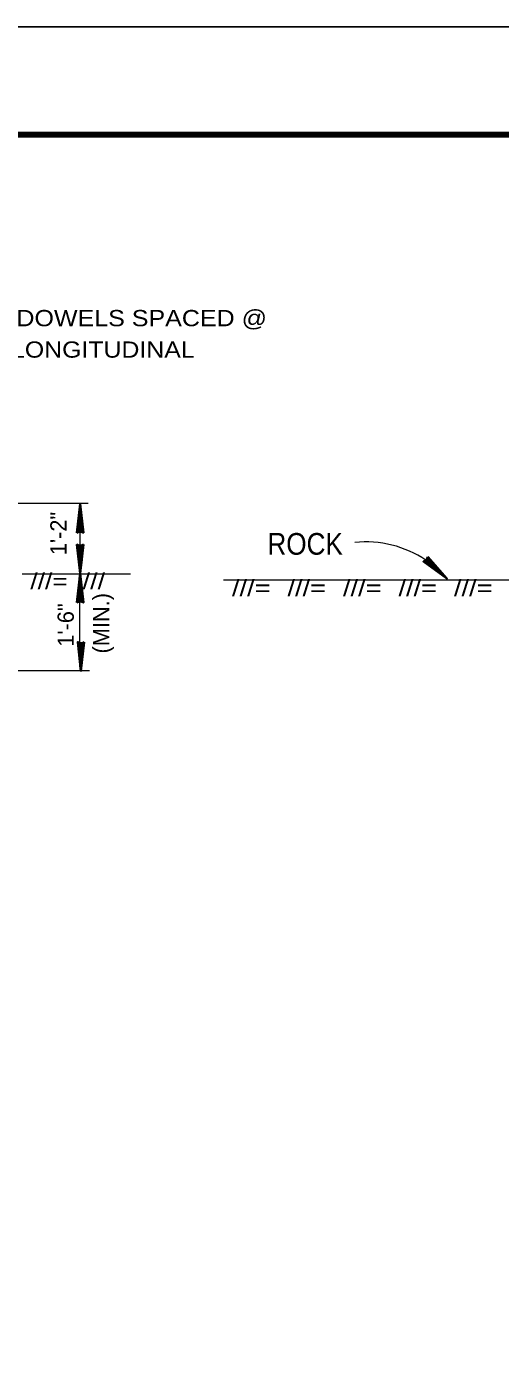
# Model space of a CAD drawing. Extents: x 1.6 to 19.9, y 2.8 to 9.5.
# Drawn here: x 18.367 to 18.709, y 8.58 to 9.545 of the extents above; entities that cross this region are included whole.
import ezdxf
from ezdxf.enums import TextEntityAlignment as Align

# ---------------------------------------------------------------- set-up
doc = ezdxf.new("R2010")
doc.units = 0
doc.header["$LTSCALE"] = 0.0047
doc.layers.add('1', color=7, linetype='Continuous', lineweight=35)
doc.layers.add('5', color=7, linetype='Continuous', lineweight=13)

msp = doc.modelspace()

# ---------------------------------------------------------------- linework, layer by layer
at = {"layer": '1', "lineweight": 25}
msp.add_line((19.894917, 9.545083), (16.26675, 9.545083), dxfattribs=at)
at = {"layer": '1', "lineweight": 13}
for p, q in [((18.209667, 9.20125), (18.411667, 9.20125)), ((18.405917, 9.1505), (18.405917, 9.198833)), ((18.402917, 9.15025), (18.411667, 9.15025)), ((18.40575, 9.083167), (18.40575, 9.149083)), ((18.22175, 9.0805), (18.412583, 9.0805))]:
    msp.add_line(p, q, dxfattribs=at)
at = {"layer": '1'}
for p, q in [((18.405917, 9.179833), (18.405917, 9.20075)), ((18.403917, 9.180333), (18.4055, 9.195917)), ((18.403917, 9.18025), (18.405583, 9.195917)), ((18.404, 9.18025), (18.405667, 9.195917)), ((18.404167, 9.18025), (18.405833, 9.19575)), ((18.404333, 9.18025), (18.406, 9.19575)), ((18.40725, 9.180167), (18.405583, 9.19475)), ((18.407417, 9.18025), (18.405917, 9.19475)), ((18.407667, 9.18025), (18.406167, 9.19475)), ((18.407917, 9.180333), (18.406333, 9.194833)), ((18.405917, 9.171333), (18.405917, 9.1505)), ((18.403917, 9.170917), (18.4055, 9.156333)), ((18.404167, 9.171), (18.405667, 9.156417)), ((18.404333, 9.171), (18.405917, 9.156417)), ((18.404583, 9.171), (18.406167, 9.1565)), ((18.407417, 9.171), (18.405833, 9.155417)), ((18.407667, 9.171), (18.406, 9.155417)), ((18.407917, 9.171), (18.406167, 9.155333)), ((18.40775, 9.171), (18.406167, 9.155333)), ((18.407917, 9.170917), (18.406333, 9.155333)), ((18.656667, 9.16175), (18.667083, 9.15)), ((18.656833, 9.161833), (18.66725, 9.150083)), ((18.656917, 9.161917), (18.667333, 9.15025)), ((18.657, 9.162), (18.667417, 9.15025)), ((18.657083, 9.162), (18.667417, 9.150333)), ((18.404917, 9.160167), (18.40575, 9.15325)), ((18.405083, 9.160167), (18.405833, 9.153417)), ((18.405167, 9.160167), (18.405917, 9.153417)), ((18.40525, 9.160167), (18.406083, 9.153417)), ((18.406667, 9.160167), (18.405833, 9.152833)), ((18.405917, 9.160333), (18.405917, 9.150583)), ((18.40675, 9.160167), (18.405917, 9.152833)), ((18.40675, 9.160167), (18.406, 9.152833)), ((18.406833, 9.160167), (18.406083, 9.152833)), ((18.406833, 9.160167), (18.406083, 9.152833)), ((18.654333, 9.159), (18.666167, 9.1505)), ((18.654417, 9.159167), (18.666333, 9.150667)), ((18.654583, 9.159417), (18.666417, 9.15075)), ((18.65475, 9.159667), (18.6665, 9.151)), ((18.655417, 9.16075), (18.670833, 9.14675)), ((18.403917, 9.13), (18.4055, 9.1455)), ((18.403917, 9.129833), (18.405583, 9.1455)), ((18.404, 9.129833), (18.405667, 9.1455)), ((18.404167, 9.129833), (18.405833, 9.145417)), ((18.404333, 9.129833), (18.406, 9.145417)), ((18.404833, 9.139417), (18.405583, 9.14675)), ((18.404833, 9.139417), (18.405583, 9.14675)), ((18.404917, 9.139417), (18.405667, 9.14675)), ((18.404917, 9.139417), (18.40575, 9.14675)), ((18.405083, 9.139417), (18.405833, 9.14675)), ((18.406417, 9.139417), (18.405583, 9.14625)), ((18.40725, 9.12975), (18.405583, 9.144333)), ((18.40575, 9.13925), (18.40575, 9.149)), ((18.406417, 9.139417), (18.40575, 9.14625)), ((18.406667, 9.139417), (18.405833, 9.14625)), ((18.405917, 9.1295), (18.405917, 9.150333)), ((18.406667, 9.139417), (18.405917, 9.14625)), ((18.407417, 9.129833), (18.405917, 9.144417)), ((18.407667, 9.129833), (18.406167, 9.144417)), ((18.407917, 9.13), (18.406333, 9.1445)), ((18.404417, 9.100417), (18.406083, 9.085917)), ((18.404667, 9.1005), (18.406167, 9.086)), ((18.404917, 9.1005), (18.406417, 9.086)), ((18.405167, 9.100583), (18.40675, 9.086)), ((18.406417, 9.100917), (18.406417, 9.08)), ((18.408, 9.1005), (18.406417, 9.085)), ((18.40825, 9.1005), (18.4065, 9.085)), ((18.408333, 9.1005), (18.406667, 9.084833)), ((18.408417, 9.1005), (18.40675, 9.084833)), ((18.4085, 9.100417), (18.406833, 9.084833))]:
    msp.add_line(p, q, dxfattribs=at)
at = {"layer": '1', "lineweight": 106}
msp.add_lwpolyline([(19.823, 7.367), (19.823, 9.467), (16.423, 9.467), (16.423, 7.367)], dxfattribs=at)
at = {"layer": '1'}
for points in [[(18.403583, 9.179833), (18.405917, 9.20075), (18.40825, 9.179833), (18.405917, 9.181)], [(18.40825, 9.171333), (18.405917, 9.1505), (18.403583, 9.171333), (18.405917, 9.17025)], [(18.656917, 9.1625), (18.670833, 9.14675), (18.653833, 9.159083), (18.656167, 9.160083)], [(18.407, 9.160333), (18.405917, 9.150583), (18.404833, 9.160333), (18.405917, 9.15975)], [(18.406083, 9.15975), (18.406083, 9.155333), (18.406, 9.155333), (18.406083, 9.15625)], [(18.403583, 9.1295), (18.405917, 9.150333), (18.40825, 9.1295), (18.405917, 9.130583)], [(18.404667, 9.13925), (18.40575, 9.149), (18.406833, 9.13925), (18.40575, 9.13975)], [(18.405583, 9.139833), (18.405583, 9.14425), (18.405667, 9.14425), (18.405583, 9.143417)], [(18.408833, 9.100917), (18.406417, 9.08), (18.404167, 9.100917), (18.406417, 9.09975)]]:
    msp.add_lwpolyline(points, close=True, dxfattribs=at)
for points in [[(18.405583, 9.18125), (18.4055, 9.190583), (18.40575, 9.190583), (18.405583, 9.18875), (18.4055, 9.18125), (18.40525, 9.18725), (18.405167, 9.181), (18.405083, 9.185417), (18.404833, 9.18075), (18.405417, 9.188), (18.40575, 9.19725), (18.406333, 9.195333), (18.406083, 9.197917), (18.406167, 9.18125), (18.406417, 9.186083), (18.406417, 9.181), (18.405667, 9.191667), (18.406833, 9.180917), (18.405667, 9.181333), (18.404167, 9.180417), (18.4045, 9.180917), (18.405417, 9.181333), (18.405167, 9.181833), (18.4045, 9.1815), (18.405917, 9.18125), (18.406833, 9.18075), (18.407917, 9.180333)], [(18.406167, 9.17), (18.406333, 9.160667), (18.406083, 9.160667), (18.406167, 9.1625), (18.406333, 9.17), (18.4065, 9.163917), (18.406667, 9.170167), (18.40675, 9.16575), (18.407, 9.170417), (18.406417, 9.16325), (18.406083, 9.153917), (18.4055, 9.155917), (18.40575, 9.15325), (18.405667, 9.17), (18.405417, 9.165083), (18.405417, 9.170167), (18.406167, 9.1595), (18.404917, 9.170333), (18.406167, 9.169833), (18.407667, 9.17075), (18.407333, 9.170333), (18.406417, 9.169833), (18.406667, 9.169417), (18.407333, 9.16975), (18.405917, 9.17), (18.404917, 9.1705), (18.403917, 9.170917)], [(18.6565, 9.160083), (18.663583, 9.153917), (18.663333, 9.15375), (18.662083, 9.155), (18.656667, 9.160167), (18.661167, 9.15625), (18.656667, 9.160583), (18.659917, 9.15775), (18.65675, 9.161), (18.661667, 9.15575), (18.668333, 9.14925), (18.6665, 9.150167), (18.668667, 9.1485), (18.656167, 9.15975), (18.659583, 9.15625), (18.655833, 9.159667), (18.664167, 9.153083), (18.6555, 9.159417), (18.656667, 9.16), (18.656917, 9.161667), (18.657083, 9.161083), (18.65675, 9.160167), (18.657333, 9.160083), (18.657417, 9.16075), (18.656333, 9.16), (18.655417, 9.1595), (18.654333, 9.159083)], [(18.406083, 9.15975), (18.406167, 9.156917), (18.406167, 9.15975), (18.406333, 9.15775), (18.406417, 9.16), (18.406167, 9.156583), (18.406, 9.15225), (18.40575, 9.153083), (18.405833, 9.151917), (18.405833, 9.15975), (18.405667, 9.1575), (18.405667, 9.15975), (18.406, 9.154833), (18.405417, 9.159833), (18.406, 9.159667), (18.406667, 9.160083), (18.4065, 9.159833), (18.406167, 9.159667), (18.406333, 9.159417), (18.406667, 9.159667), (18.405917, 9.15975), (18.405417, 9.16), (18.404917, 9.160167)], [(18.405583, 9.130917), (18.4055, 9.140167), (18.40575, 9.140167), (18.405583, 9.138417), (18.4055, 9.130917), (18.40525, 9.136917), (18.405167, 9.130667), (18.405083, 9.135), (18.404833, 9.130417), (18.405417, 9.137583), (18.40575, 9.146917), (18.406333, 9.145), (18.406083, 9.1475), (18.406167, 9.130917), (18.406417, 9.13575), (18.406417, 9.130667), (18.405667, 9.14125), (18.406833, 9.1305), (18.405667, 9.131), (18.404167, 9.13), (18.4045, 9.1305), (18.405417, 9.131), (18.405167, 9.131417), (18.4045, 9.131083), (18.405917, 9.13075), (18.406833, 9.130333), (18.407917, 9.13)], [(18.405583, 9.139833), (18.405417, 9.142667), (18.405417, 9.13975), (18.405417, 9.141833), (18.405167, 9.139667), (18.4055, 9.143), (18.405667, 9.147333), (18.405917, 9.1465), (18.405833, 9.147667), (18.405833, 9.139833), (18.406, 9.142167), (18.406, 9.13975), (18.405667, 9.14475), (18.406167, 9.13975), (18.405667, 9.14), (18.404917, 9.1395), (18.405167, 9.13975), (18.4055, 9.14), (18.405417, 9.140167), (18.405083, 9.14), (18.40575, 9.139833), (18.406167, 9.139667), (18.406667, 9.139417)], [(18.40675, 9.0995), (18.406833, 9.090167), (18.406667, 9.090167), (18.40675, 9.092), (18.406833, 9.0995), (18.407083, 9.0935), (18.407167, 9.09975), (18.407333, 9.095333), (18.407583, 9.1), (18.407, 9.09275), (18.406667, 9.0835), (18.406083, 9.085417), (18.406333, 9.082833), (18.406167, 9.0995), (18.405917, 9.094667), (18.405917, 9.09975), (18.406667, 9.089083), (18.4055, 9.099833), (18.406667, 9.099417), (18.408167, 9.100333), (18.407917, 9.099833), (18.407, 9.099417), (18.40725, 9.098917), (18.407917, 9.09925), (18.406417, 9.0995), (18.4055, 9.1), (18.4045, 9.100417)]]:
    msp.add_lwpolyline(points, dxfattribs=at)
at = {"layer": '1', "lineweight": 13}
msp.add_arc((18.61212, 9.094891), 0.078393, 56.26433, 95.70423, dxfattribs=at)
at = {"layer": '5'}
for p, q in [((18.364, 9.15025), (18.442167, 9.15025)), ((18.5095, 9.145917), (19.235667, 9.145917))]:
    msp.add_line(p, q, dxfattribs=at)

# ---------------------------------------------------------------- texts
for s, height, width, p in [('#8 DOWELS SPACED @', 0.01175, 1.15, (18.33475, 9.328917)), ("2' LONGITUDINAL", 0.01167, 1.15, (18.337583, 9.30625)), ('ROCK', 0.01567, 0.9, (18.541167, 9.164)), ('///', 0.01167, 1.25, (18.407667, 9.139083))]:
    msp.add_text(s, height=height, dxfattribs=dict(at, width=width)).set_placement(p)
for s, p in [('1\'-2"', (18.396083, 9.179333)), ('(MIN.)', (18.426917, 9.114542)), ('1\'-6"', (18.401333, 9.11325))]:
    msp.add_text(s, height=0.01175, rotation=90, dxfattribs=at).set_placement(p, align=Align.CENTER)
at = {"layer": '5', "width": 1.25}
for height, p in [(0.01142, (18.383417, 9.139167)), (0.01175, (18.5295, 9.134167)), (0.01175, (18.569583, 9.134167)), (0.01175, (18.609667, 9.134167)), (0.01175, (18.64975, 9.134167)), (0.01175, (18.689833, 9.134167))]:
    msp.add_text('///=', height=height, dxfattribs=at).set_placement(p, align=Align.CENTER)

doc.saveas('drawing.dxf')
